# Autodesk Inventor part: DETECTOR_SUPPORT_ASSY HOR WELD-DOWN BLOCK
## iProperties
Shininess: 64.0
Length Units: 11272
Angle Units: 11279
Time Units: 11290
Mass Units: 11286
Length Display Precision: 3
Angle Display Precision: 2
Compacted: True
Part Number: DETECTOR_SUPPORT_ASSY HOR WELD-DOWN BLOCK
Document SubType Name: Modeling
Created: 2004-08
Designer: John Blackburn
Material: MILD_STEEL
Manufacturer: Standard
Standards Organization: Custom
Density: 0.0
Volumn: 0.0
Area: 0.0
PropertySet Name: Model Information
Control State: 0
Master: False
Checked Out: False
Author: John Blackburn
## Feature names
1. ExtrusionBlind1
2. AM_HOLE_SI0030_1 [Hole]
